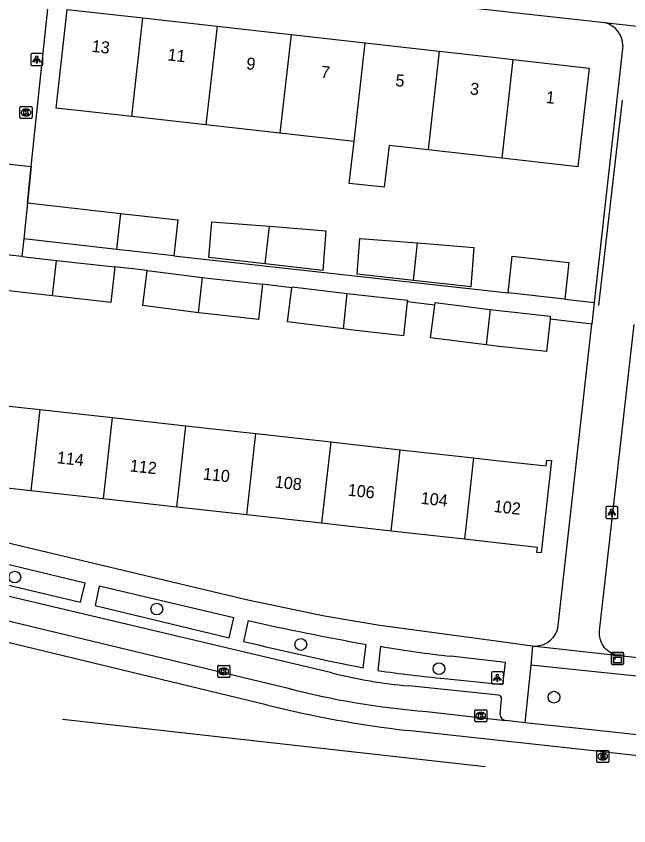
# Model space of a CAD drawing. Extents: x 162026 to 163499, y 387297 to 388169.
# Drawn here: x 162460.1 to 162511, y 387370.4 to 387437.6 of the extents above; entities that cross this region are included whole.
import ezdxf

# ---------------------------------------------------------------- set-up
doc = ezdxf.new("R2010")
doc.units = 0
for name, color, linetype in [('IMGEO_Boom', 7, 'Continuous'), ('IMGEO_Kast', 7, 'Continuous'), ('IMGEO_Kolk', 7, 'Continuous'), ('IMGEO_Lichtpunt', 7, 'Continuous'), ('IMGEO_Muur', 7, 'Continuous'), ('IMGEO_Pand', 7, 'Continuous'), ('IMGEO_Pand_nummerreeks', 7, 'Continuous'), ('IMGEO_Rijbaan_lokaal_gesloten', 7, 'Continuous'), ('IMGEO_Rijbaan_lokaal_open', 7, 'Continuous'), ('IMGEO_Rioolput', 7, 'Continuous'), ('IMGEO_Voetpad_open', 7, 'Continuous')]:
    doc.layers.add(name, color=color, linetype=linetype)

msp = doc.modelspace()

# ---------------------------------------------------------------- linework, layer by layer
at = {"layer": 'IMGEO_Boom'}
for centre in [(162460.031, 387391.034), (162471.823, 387388.377), (162483.783, 387385.441), (162495.259, 387383.432), (162504.808, 387381.061)]:
    msp.add_circle(centre, 0.489, dxfattribs=at)
at = {"layer": 'IMGEO_Kast'}
for p, q in [((162509.585, 387383.858), (162509.585, 387384.699)), ((162509.585, 387384.699), (162509.585, 387383.858)), ((162509.66, 387384.783), (162510.501, 387384.783)), ((162510.501, 387384.783), (162509.66, 387384.783)), ((162510.585, 387384.708), (162510.585, 387383.867)), ((162510.585, 387383.867), (162510.585, 387384.708)), ((162510.51, 387383.783), (162509.669, 387383.783)), ((162509.669, 387383.783), (162510.51, 387383.783))]:
    msp.add_line(p, q, dxfattribs=at)
for points in [[(162509.78, 387384.573), (162510.38, 387384.573), (162510.38, 387384.488), (162509.78, 387384.488), (162509.78, 387384.573)], [(162509.78, 387384.398), (162510.38, 387384.398), (162510.38, 387383.909), (162509.78, 387383.909), (162509.78, 387384.398)]]:
    msp.add_lwpolyline(points, dxfattribs=at)
msp.add_circle((162509.864, 387384.247), 0.0377, dxfattribs=at)
for centre, start, end in [((162509.663, 387384.705), 92.4484, 184.28452), ((162509.663, 387384.705), 92.4484, 184.28452), ((162510.507, 387384.705), 2.4484, 94.28452), ((162510.507, 387384.705), 2.4484, 94.28452), ((162510.507, 387383.861), 272.4484, 4.28452), ((162510.507, 387383.861), 272.4484, 4.28452), ((162509.663, 387383.861), 182.4484, 274.28452), ((162509.663, 387383.861), 182.4484, 274.28452)]:
    msp.add_arc(centre, 0.0779, start, end, dxfattribs=at)
at = {"layer": 'IMGEO_Kolk'}
for p, q in [((162460.459, 387429.195), (162460.459, 387430.047)), ((162460.534, 387430.121), (162461.386, 387430.121)), ((162460.947, 387429.901), (162460.972, 387429.901)), ((162461.46, 387430.047), (162461.46, 387429.195)), ((162461.386, 387429.121), (162460.534, 387429.121)), ((162460.97, 387429.341), (162460.945, 387429.341)), ((162476.889, 387382.779), (162476.889, 387383.631)), ((162476.964, 387383.705), (162477.816, 387383.705)), ((162477.377, 387383.485), (162477.402, 387383.485)), ((162477.89, 387383.631), (162477.89, 387382.779)), ((162477.816, 387382.705), (162476.964, 387382.705)), ((162477.4, 387382.925), (162477.375, 387382.925)), ((162498.23, 387379.092), (162498.23, 387379.944)), ((162498.305, 387380.018), (162499.157, 387380.018)), ((162499.231, 387379.944), (162499.231, 387379.092)), ((162498.741, 387379.238), (162498.716, 387379.238)), ((162498.718, 387379.798), (162498.743, 387379.798)), ((162499.157, 387379.018), (162498.305, 387379.018))]:
    msp.add_line(p, q, dxfattribs=at)
for points in [[(162460.459, 387429.195), (162460.459, 387430.047)], [(162460.534, 387430.121), (162461.386, 387430.121)], [(162460.78, 387429.821), (162460.903, 387429.821), (162460.903, 387429.67), (162461.033, 387429.821), (162461.197, 387429.821), (162461.051, 387429.67), (162461.204, 387429.421), (162461.052, 387429.421), (162460.967, 387429.585), (162460.903, 387429.518), (162460.903, 387429.421), (162460.78, 387429.421), (162460.78, 387429.821)], [(162461.46, 387430.047), (162461.46, 387429.195)], [(162461.386, 387429.121), (162460.534, 387429.121)], [(162476.889, 387382.779), (162476.889, 387383.631)], [(162476.964, 387383.705), (162477.816, 387383.705)], [(162477.21, 387383.405), (162477.333, 387383.405), (162477.333, 387383.254), (162477.463, 387383.405), (162477.627, 387383.405), (162477.481, 387383.254), (162477.634, 387383.005), (162477.482, 387383.005), (162477.397, 387383.169), (162477.333, 387383.102), (162477.333, 387383.005), (162477.21, 387383.005), (162477.21, 387383.405)], [(162477.89, 387383.631), (162477.89, 387382.779)], [(162477.816, 387382.705), (162476.964, 387382.705)], [(162498.23, 387379.092), (162498.23, 387379.944)], [(162498.305, 387380.018), (162499.157, 387380.018)], [(162499.231, 387379.944), (162499.231, 387379.092)], [(162498.551, 387379.718), (162498.674, 387379.718), (162498.674, 387379.567), (162498.804, 387379.718), (162498.968, 387379.718), (162498.822, 387379.567), (162498.975, 387379.318), (162498.823, 387379.318), (162498.738, 387379.482), (162498.674, 387379.415), (162498.674, 387379.318), (162498.551, 387379.318), (162498.551, 387379.718)], [(162499.157, 387379.018), (162498.305, 387379.018)]]:
    msp.add_lwpolyline(points, dxfattribs=at)
for centre, start, end in [((162460.536, 387430.045), 91.55205, 178.44795), ((162460.536, 387430.045), 91.55205, 178.44795), ((162461.384, 387430.045), 1.55205, 88.44795), ((162461.384, 387430.045), 1.55205, 88.44795), ((162460.536, 387429.197), 181.55205, 268.44795), ((162460.536, 387429.197), 181.55205, 268.44795), ((162461.384, 387429.197), 271.55205, 358.44795), ((162461.384, 387429.197), 271.55205, 358.44795), ((162476.966, 387383.629), 91.55205, 178.44795), ((162476.966, 387383.629), 91.55205, 178.44795), ((162477.814, 387383.629), 1.55205, 88.44795), ((162477.814, 387383.629), 1.55205, 88.44795), ((162476.966, 387382.781), 181.55205, 268.44795), ((162476.966, 387382.781), 181.55205, 268.44795), ((162477.814, 387382.781), 271.55205, 358.44795), ((162477.814, 387382.781), 271.55205, 358.44795), ((162498.307, 387379.942), 91.55205, 178.44795), ((162498.307, 387379.942), 91.55205, 178.44795), ((162499.155, 387379.942), 1.55205, 88.44795), ((162499.155, 387379.942), 1.55205, 88.44795), ((162498.307, 387379.094), 181.55205, 268.44795), ((162498.307, 387379.094), 181.55205, 268.44795), ((162499.155, 387379.094), 271.55205, 358.44795), ((162499.155, 387379.094), 271.55205, 358.44795)]:
    msp.add_arc(centre, 0.0765, start, end, dxfattribs=at)
for centre, major_axis, ratio, start_param, end_param in [((162460.946, 387429.621), (-0.387, 0.002), 0.722429, 4.712389, 7.853982), ((162460.971, 387429.621), (-0.39, 0.002), 0.717154, 1.570796, 4.712389), ((162477.376, 387383.205), (-0.387, 0.002), 0.722429, 4.712389, 7.853982), ((162477.401, 387383.205), (-0.39, 0.002), 0.717154, 1.570796, 4.712389), ((162498.717, 387379.518), (-0.387, 0.002), 0.722429, 4.712389, 7.853982), ((162498.742, 387379.518), (-0.39, 0.002), 0.717154, 1.570796, 4.712389)]:
    msp.add_ellipse(centre, major_axis=major_axis, ratio=ratio, start_param=start_param, end_param=end_param, dxfattribs=at)
at = {"layer": 'IMGEO_Lichtpunt'}
for p, q in [((162461.352, 387434.43), (162461.352, 387433.623)), ((162461.352, 387434.43), (162461.352, 387433.623)), ((162462.254, 387434.525), (162461.446, 387434.525)), ((162462.254, 387434.525), (162461.446, 387434.525)), ((162462.348, 387433.623), (162462.348, 387434.43)), ((162462.348, 387433.623), (162462.348, 387434.43)), ((162461.446, 387433.529), (162462.254, 387433.529)), ((162461.446, 387433.529), (162462.254, 387433.529)), ((162509.11, 387396.809), (162509.11, 387396.002)), ((162509.11, 387396.809), (162509.11, 387396.002)), ((162510.012, 387396.904), (162509.204, 387396.904)), ((162510.012, 387396.904), (162509.204, 387396.904)), ((162510.106, 387396.002), (162510.106, 387396.809)), ((162510.106, 387396.002), (162510.106, 387396.809)), ((162509.204, 387395.908), (162510.012, 387395.908)), ((162509.204, 387395.908), (162510.012, 387395.908)), ((162499.609, 387383.066), (162499.609, 387382.259)), ((162499.609, 387383.066), (162499.609, 387382.259)), ((162500.511, 387383.161), (162499.703, 387383.161)), ((162500.511, 387383.161), (162499.703, 387383.161)), ((162500.605, 387382.259), (162500.605, 387383.066)), ((162500.605, 387382.259), (162500.605, 387383.066)), ((162499.703, 387382.165), (162500.511, 387382.165)), ((162499.703, 387382.165), (162500.511, 387382.165))]:
    msp.add_line(p, q, dxfattribs=at)
for points in [[(162461.726, 387434.094), (162461.765, 387434.066), (162461.577, 387433.804), (162461.539, 387433.831), (162461.726, 387434.094)], [(162461.828, 387434.046), (162461.875, 387434.046), (162461.875, 387433.724), (162461.828, 387433.724), (162461.828, 387434.046)], [(162461.938, 387434.066), (162461.976, 387434.093), (162462.163, 387433.831), (162462.124, 387433.803), (162461.938, 387434.066)], [(162509.484, 387396.473), (162509.523, 387396.445), (162509.335, 387396.183), (162509.297, 387396.21), (162509.484, 387396.473)], [(162509.586, 387396.425), (162509.633, 387396.425), (162509.633, 387396.103), (162509.586, 387396.103), (162509.586, 387396.425)], [(162509.696, 387396.445), (162509.734, 387396.472), (162509.921, 387396.21), (162509.882, 387396.182), (162509.696, 387396.445)], [(162499.983, 387382.73), (162500.022, 387382.702), (162499.834, 387382.44), (162499.796, 387382.467), (162499.983, 387382.73)], [(162500.085, 387382.682), (162500.132, 387382.682), (162500.132, 387382.36), (162500.085, 387382.36), (162500.085, 387382.682)], [(162500.195, 387382.702), (162500.233, 387382.729), (162500.42, 387382.467), (162500.381, 387382.439), (162500.195, 387382.702)]]:
    msp.add_lwpolyline(points, dxfattribs=at)
for centre in [(162461.851, 387434.228), (162509.609, 387396.607), (162500.108, 387382.864)]:
    msp.add_circle(centre, 0.0994, dxfattribs=at)
for centre, start, end in [((162461.446, 387434.43), 90, 180), ((162461.446, 387434.43), 90, 180), ((162462.254, 387434.43), 0, 90), ((162462.254, 387434.43), 0, 90), ((162461.446, 387433.623), 180, 270), ((162461.446, 387433.623), 180, 270), ((162462.254, 387433.623), 270, 0), ((162462.254, 387433.623), 270, 360), ((162509.204, 387396.809), 90, 180), ((162509.204, 387396.809), 90, 180), ((162510.012, 387396.809), 0, 90), ((162510.012, 387396.809), 0, 90), ((162509.204, 387396.002), 180, 270), ((162509.204, 387396.002), 180, 270), ((162510.012, 387396.002), 270, 0), ((162510.012, 387396.002), 270, 360), ((162499.703, 387383.066), 90, 180), ((162499.703, 387383.066), 90, 180), ((162500.511, 387383.066), 0, 90), ((162500.511, 387383.066), 0, 90), ((162499.703, 387382.259), 180, 270), ((162499.703, 387382.259), 180, 270), ((162500.511, 387382.259), 270, 0), ((162500.511, 387382.259), 270, 360)]:
    msp.add_arc(centre, 0.0946, start, end, dxfattribs=at)
at = {"layer": 'IMGEO_Muur'}
for points in [[(162508.53, 387413.588), (162510.488, 387430.63)], [(162461.4, 387425.126), (162461.926, 387430.151)], [(162461.084, 387422.106), (162461.4, 387425.126)]]:
    msp.add_lwpolyline(points, dxfattribs=at)
at = {"layer": 'IMGEO_Pand'}
for points in [[(162469.753, 387429.283), (162463.458, 387429.991), (162464.379, 387438.183), (162470.674, 387437.475)], [(162469.753, 387429.283), (162470.674, 387437.475)], [(162470.674, 387437.475), (162476.823, 387436.784)], [(162476.823, 387436.784), (162475.902, 387428.592)], [(162476.823, 387436.784), (162482.973, 387436.092)], [(162482.973, 387436.092), (162482.052, 387427.9)], [(162482.973, 387436.092), (162489.122, 387435.401)], [(162488.201, 387427.209), (162489.122, 387435.401)], [(162489.122, 387435.401), (162495.271, 387434.71)], [(162495.271, 387434.71), (162494.35, 387426.517)], [(162495.271, 387434.71), (162500, 387434.178), (162501.42, 387434.018)], [(162501.42, 387434.018), (162507.718, 387433.31), (162506.797, 387425.118), (162500.499, 387425.826)], [(162500.499, 387425.826), (162501.42, 387434.018)], [(162475.902, 387428.592), (162469.753, 387429.283)], [(162482.052, 387427.9), (162475.902, 387428.592)], [(162488.201, 387427.209), (162482.052, 387427.9)], [(162494.35, 387426.517), (162491.11, 387426.882), (162490.719, 387423.407), (162487.81, 387423.734), (162488.201, 387427.209)], [(162500.499, 387425.826), (162500, 387425.882), (162494.35, 387426.517)], [(162461.084, 387422.106), (162460.771, 387419.117)], [(162461.084, 387422.106), (162468.848, 387421.233)], [(162468.512, 387418.246), (162468.848, 387421.233)], [(162468.848, 387421.233), (162473.565, 387420.703), (162473.229, 387417.716)], [(162480.831, 387417.047), (162476.158, 387417.571), (162476.393, 387420.544), (162481.182, 387420.166)], [(162481.182, 387420.166), (162485.862, 387419.797), (162485.603, 387416.511), (162480.831, 387417.047)], [(162480.831, 387417.047), (162481.182, 387420.166)], [(162468.512, 387418.246), (162460.771, 387419.117)], [(162493.13, 387415.663), (162488.456, 387416.188), (162488.691, 387419.161), (162493.481, 387418.783)], [(162473.229, 387417.716), (162468.512, 387418.246)], [(162493.481, 387418.783), (162498.16, 387418.414), (162497.901, 387415.128), (162493.13, 387415.663)], [(162493.13, 387415.663), (162493.481, 387418.783)], [(162463.154, 387414.388), (162458.509, 387414.91), (162458.84, 387417.856)], [(162460.618, 387417.656), (162458.84, 387417.856)], [(162460.618, 387417.656), (162463.482, 387417.334)], [(162500.991, 387414.639), (162501.327, 387417.676), (162506.042, 387417.154), (162505.706, 387414.116)], [(162463.154, 387414.388), (162463.482, 387417.334)], [(162463.482, 387417.334), (162468.344, 387416.788)], [(162468.344, 387416.788), (162468.013, 387413.842), (162463.154, 387414.388)], [(162475.282, 387412.991), (162470.655, 387413.579), (162471.029, 387416.492)], [(162471.029, 387416.492), (162475.61, 387415.929)], [(162475.282, 387412.991), (162475.61, 387415.929)], [(162475.61, 387415.929), (162476.097, 387415.869), (162480.603, 387415.37)], [(162480.603, 387415.37), (162480.277, 387412.424), (162476.097, 387412.887), (162475.282, 387412.991)], [(162487.315, 387411.65), (162482.688, 387412.238), (162483.049, 387415.046)], [(162483.049, 387415.046), (162483.062, 387415.151), (162487.643, 387414.588)], [(162487.315, 387411.65), (162487.643, 387414.588)], [(162487.643, 387414.588), (162488.13, 387414.528), (162492.636, 387414.029), (162492.621, 387413.894)], [(162505.706, 387414.116), (162500.991, 387414.639)], [(162492.621, 387413.894), (162492.31, 387411.083), (162488.13, 387411.546), (162487.315, 387411.65)], [(162499.185, 387410.327), (162494.558, 387410.915), (162494.905, 387413.619)], [(162494.905, 387413.619), (162494.932, 387413.828), (162499.513, 387413.265)], [(162499.513, 387413.265), (162499.185, 387410.327)], [(162499.513, 387413.265), (162500, 387413.205), (162504.506, 387412.706), (162504.48, 387412.467)], [(162504.48, 387412.467), (162504.18, 387409.76), (162500, 387410.223), (162499.185, 387410.327)], [(162461.349, 387398.198), (162455.662, 387398.832), (162455.616, 387398.412), (162455.257, 387398.452), (162456.12, 387406.188), (162456.59, 387406.135), (162456.527, 387405.573), (162462.102, 387404.952)], [(162462.102, 387404.952), (162461.349, 387398.198)], [(162462.102, 387404.952), (162468.12, 387404.281)], [(162468.12, 387404.281), (162467.367, 387397.527)], [(162468.12, 387404.281), (162474.235, 387403.599)], [(162473.482, 387396.845), (162474.235, 387403.599)], [(162474.235, 387403.599), (162480.044, 387402.952)], [(162479.291, 387396.198), (162480.044, 387402.952)], [(162480.044, 387402.952), (162486.268, 387402.258)], [(162486.268, 387402.258), (162485.515, 387395.504)], [(162486.268, 387402.258), (162492.036, 387401.615)], [(162491.283, 387394.861), (162492.036, 387401.615)], [(162492.036, 387401.615), (162498.138, 387400.935)], [(162498.138, 387400.935), (162500, 387400.727), (162504.16, 387400.263), (162504.214, 387400.749), (162504.608, 387400.705), (162503.753, 387393.04), (162503.388, 387393.081), (162503.435, 387393.506), (162500, 387393.889), (162497.385, 387394.181)], [(162498.138, 387400.935), (162497.385, 387394.181)], [(162467.367, 387397.527), (162461.349, 387398.198)], [(162473.482, 387396.845), (162467.367, 387397.527)], [(162479.291, 387396.198), (162473.482, 387396.845)], [(162485.515, 387395.504), (162479.291, 387396.198)], [(162491.283, 387394.861), (162485.515, 387395.504)], [(162497.385, 387394.181), (162491.283, 387394.861)]]:
    msp.add_lwpolyline(points, dxfattribs=at)
at = {"layer": 'IMGEO_Rijbaan_lokaal_gesloten'}
for points in [[(162481.027, 387380.405), (162452.771, 387387.216), (162400.227, 387399.776), (162389.995, 387402.241), (162380.574, 387405.433)], [(162453.238, 387388.898), (162482.612, 387381.839)], [(162494.229, 387379.882), (162500.773, 387379.123)], [(162463.978, 387379.236), (162499.096, 387375.311), (162499.096, 387375.311)], [(162502.394, 387378.935), (162500.773, 387379.123)], [(162515.504, 387377.53), (162507.888, 387378.356), (162502.394, 387378.935)], [(162564.23, 387370.379), (162559.818, 387370.862), (162518.186, 387375.46), (162507.846, 387376.647), (162492.641, 387378.303)]]:
    msp.add_lwpolyline(points, dxfattribs=at)
for centre, radius, start, end in [((162498.98, 387443.546), 63.841, 255.14376, 265.7317), ((162502.629, 387466.622), 88.882, 255.93421, 263.54815)]:
    msp.add_arc(centre, radius, start, end, dxfattribs=at)
at = {"layer": 'IMGEO_Rijbaan_lokaal_open'}
for points in [[(162456.91, 387425.623), (162461.4, 387425.126)], [(162461.4, 387425.126), (162461.084, 387422.106)], [(162460.771, 387419.117), (162460.618, 387417.656)]]:
    msp.add_lwpolyline(points, dxfattribs=at)
at = {"layer": 'IMGEO_Rioolput'}
for p, q in [((162508.358, 387375.714), (162508.358, 387376.566)), ((162508.433, 387376.64), (162509.285, 387376.64)), ((162509.359, 387376.566), (162509.359, 387375.714)), ((162508.869, 387375.86), (162508.844, 387375.86)), ((162508.846, 387376.42), (162508.871, 387376.42)), ((162509.285, 387375.64), (162508.433, 387375.64))]:
    msp.add_line(p, q, dxfattribs=at)
for points in [[(162508.358, 387375.714), (162508.358, 387376.566)], [(162508.433, 387376.64), (162509.285, 387376.64)], [(162509.359, 387376.566), (162509.359, 387375.714)], [(162508.947, 387376.338), (162508.695, 387376.34), (162508.695, 387375.94)], [(162508.695, 387375.94), (162508.819, 387375.94), (162508.819, 387376.102), (162508.83, 387376.102)], [(162508.873, 387376.259), (162508.819, 387376.259), (162508.819, 387376.178)], [(162508.819, 387376.178), (162508.871, 387376.178)], [(162508.877, 387376.073), (162508.948, 387375.94), (162509.088, 387375.94), (162509.023, 387376.066)], [(162509.285, 387375.64), (162508.433, 387375.64)]]:
    msp.add_lwpolyline(points, dxfattribs=at)
for centre, radius, start, end in [((162508.435, 387376.564), 0.0765, 91.55205, 178.44795), ((162508.435, 387376.564), 0.0765, 91.55205, 178.44795), ((162509.283, 387376.564), 0.0765, 1.55205, 88.44795), ((162509.283, 387376.564), 0.0765, 1.55205, 88.44795), ((162508.829, 387376.049), 0.0533, 26.02933, 88.69889), ((162508.855, 387376.367), 0.19, 274.7715, 282.96867), ((162508.879, 387376.163), 0.0964, 77.00612, 93.18647), ((162508.893, 387376.22), 0.0378, 276.66336, 79.67722), ((162508.946, 387376.228), 0.109, 350.36119, 89.41601), ((162508.944, 387376.228), 0.112, 277.58423, 350.98172), ((162508.928, 387376.013), 0.108, 29.51342, 73.79051), ((162508.435, 387375.716), 0.0765, 181.55205, 268.44795), ((162508.435, 387375.716), 0.0765, 181.55205, 268.44795), ((162509.283, 387375.716), 0.0765, 271.55205, 358.44795), ((162509.283, 387375.716), 0.0765, 271.55205, 358.44795)]:
    msp.add_arc(centre, radius, start, end, dxfattribs=at)
for centre, major_axis, ratio, start_param, end_param in [((162508.845, 387376.14), (-0.387, 0.002), 0.722429, 4.712389, 7.853982), ((162508.87, 387376.14), (-0.39, 0.002), 0.717154, 1.570796, 4.712389)]:
    msp.add_ellipse(centre, major_axis=major_axis, ratio=ratio, start_param=start_param, end_param=end_param, dxfattribs=at)
at = {"layer": 'IMGEO_Voetpad_open'}
for points in [[(162461.4, 387425.126), (162461.926, 387430.151), (162463.184, 387442.149), (162465.999, 387441.839)], [(162465.999, 387441.839), (162500, 387438.095), (162509.017, 387437.102)], [(162509.017, 387437.102), (162515.847, 387436.309)], [(162510.534, 387435.171), (162508.158, 387413.846)], [(162473.229, 387417.716), (162500.991, 387414.639)], [(162471.029, 387416.492), (162468.344, 387416.788)], [(162483.049, 387415.046), (162480.603, 387415.37)], [(162494.905, 387413.619), (162492.621, 387413.894)], [(162505.706, 387414.116), (162508.158, 387413.846)], [(162508.158, 387413.846), (162507.958, 387412.048)], [(162507.958, 387412.048), (162504.48, 387412.467)], [(162505.17, 387387.017), (162507.958, 387412.048)], [(162509.987, 387384.553), (162509.827, 387384.602), (162509.673, 387384.665), (162509.524, 387384.741), (162509.383, 387384.831), (162509.25, 387384.932), (162509.127, 387385.046), (162509.015, 387385.169), (162508.914, 387385.302), (162508.826, 387385.444), (162508.75, 387385.593), (162508.688, 387385.748), (162508.64, 387385.908), (162508.607, 387386.072), (162508.588, 387386.238), (162508.585, 387386.405), (162508.596, 387386.572), (162511.463, 387412.025)], [(162452.941, 387395.422), (162479.373, 387389.141), (162485.737, 387387.815), (162490.344, 387387.037), (162500, 387385.729), (162503.031, 387385.319)], [(162454.583, 387393.24), (162454.219, 387391.622), (162465.495, 387388.949), (162465.87, 387390.543), (162454.583, 387393.24)], [(162486.36, 387383.07), (162454.39, 387390.648)], [(162467.038, 387390.278), (162466.694, 387388.662), (162477.825, 387385.978), (162478.227, 387387.659), (162467.038, 387390.278)], [(162479.414, 387387.417), (162479.029, 387385.694)], [(162488.962, 387383.505), (162489.203, 387385.449)], [(162490.413, 387385.285), (162490.172, 387383.268)], [(162503.031, 387385.319), (162502.899, 387383.719)], [(162503.26, 387385.31), (162509.987, 387384.553)], [(162514.853, 387383.996), (162510.251, 387384.505), (162510.151, 387384.519), (162509.987, 387384.553)], [(162495.724, 387382.605), (162500.567, 387382.109), (162500.794, 387383.935), (162496.235, 387384.466)], [(162502.899, 387383.719), (162502.394, 387378.935)], [(162515.504, 387377.53), (162515.843, 387380.694), (162515.685, 387380.71), (162515.866, 387382.364), (162510.06, 387382.973), (162502.899, 387383.719)], [(162500.208, 387381.232), (162492.746, 387382.005)], [(162500.341, 387379.609), (162500.45, 387380.916)]]:
    msp.add_lwpolyline(points, dxfattribs=at)
for centre, radius, start, end in [((162508.487, 387435.124), 2.047, 1.30657, 75.00002), ((162529.021, 387608.836), 226.908, 257.37195, 259.8934), ((162503.22, 387387.277), 1.968, 271.17462, 352.4008), ((162532.164, 387603.172), 223.875, 256.27033, 258.87368), ((162505.475, 387471.25), 87.274, 260.06229, 263.92282), ((162503.219, 387387.178), 1.868, 264.23339, 271.26532), ((162510.257, 387527.879), 145.999, 262.09297, 264.28741), ((162496.309, 387423.047), 41.196, 256.02505, 265.03867), ((162500.15, 387380.937), 0.301, 356.05064, 78.84079), ((162500.848, 387379.624), 0.507, 181.75098, 261.5161)]:
    msp.add_arc(centre, radius, start, end, dxfattribs=at)

# ---------------------------------------------------------------- texts
at = {"layer": 'IMGEO_Pand_nummerreeks'}
for s, rotation, p in [('13', 353.58466, (162466.378, 387434.658)), ('11', 353.58466, (162472.682, 387433.949)), ('9', 353.58466, (162479.217, 387433.214)), ('7', 353.58466, (162485.408, 387432.518)), ('5', 353.58466, (162491.6, 387431.822)), ('3', 353.58466, (162497.791, 387431.125)), ('1', 353.58466, (162504.095, 387430.416)), ('114', 353.63867, (162463.488, 387400.495)), ('112', 353.63867, (162469.546, 387399.82)), ('110', 353.63867, (162475.614, 387399.143)), ('108', 353.63867, (162481.586, 387398.477)), ('106', 353.63867, (162487.645, 387397.802)), ('104', 353.63867, (162493.707, 387397.126)), ('102', 353.63867, (162499.767, 387396.45))]:
    msp.add_text(s, height=1, rotation=rotation, dxfattribs=at).set_placement(p)

doc.saveas('drawing.dxf')
